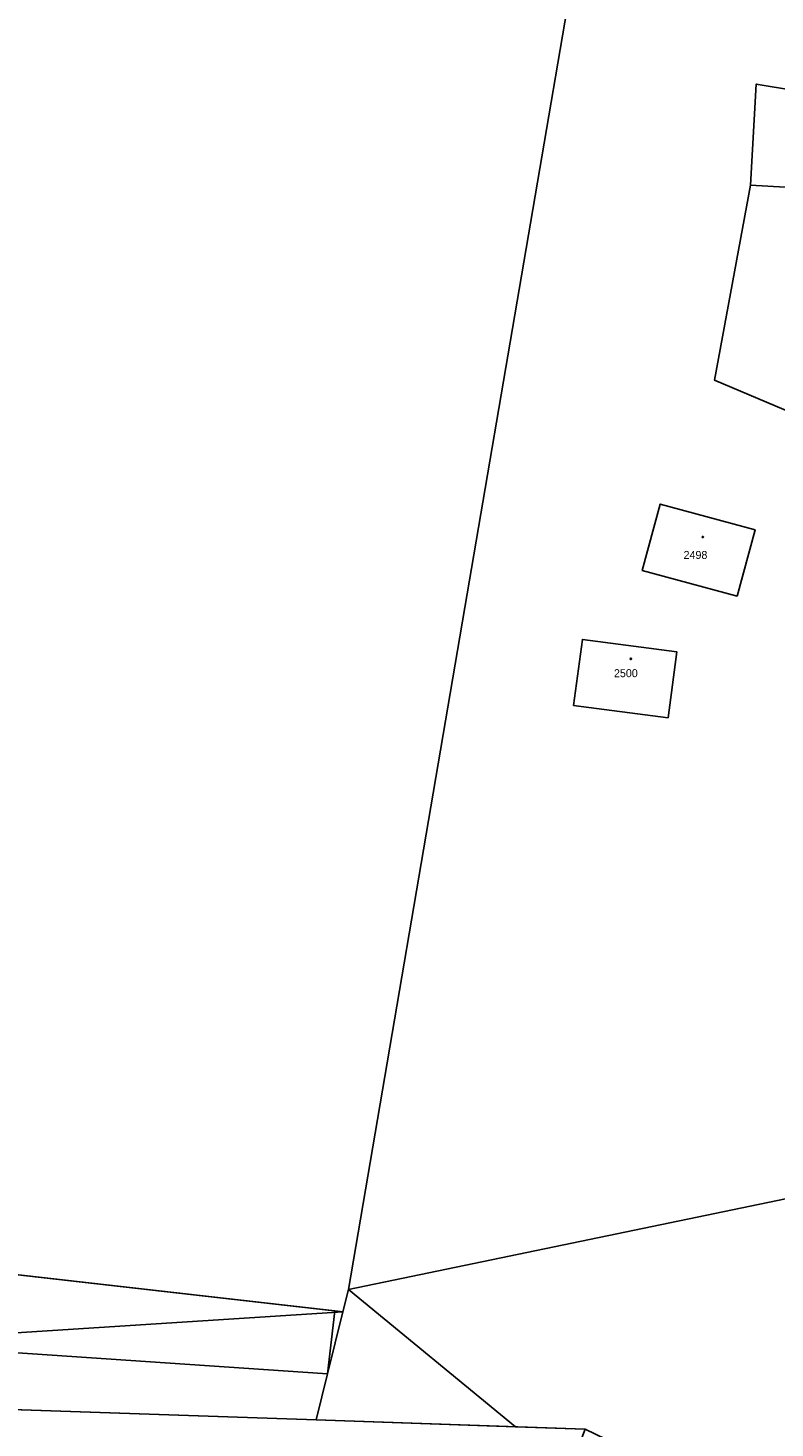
# Model space of a CAD drawing. Extents: x -439750 to -439180, y -1258684 to -1258308.
# Drawn here: x -439415 to -439377.6, y -1258499.7 to -1258429.7 of the extents above; entities that cross this region are included whole.
import ezdxf

# ---------------------------------------------------------------- set-up
doc = ezdxf.new("R2010")
doc.units = 0
doc.layers.add('KATASTER', color=7, linetype='Continuous')
doc.layers.add('UOV', color=7, linetype='Continuous')

# ---------------------------------------------------------------- blocks, each defined once
blk = doc.blocks.new('402')
blk.add_lwpolyline([(0.09, 0.15), (0.18, 0), (0.09, -0.15), (-0.09, -0.15), (-0.18, 0), (-0.09, 0.15), (0.09, 0.15)])

msp = doc.modelspace()

# ---------------------------------------------------------------- linework, layer by layer
at = {"layer": 'KATASTER'}
msp.add_line((-439399.61, -1258493.83), (-439399.97, -1258496.98), dxfattribs=at)
for points in [[(-439342.84, -1258481.76), (-439376.6, -1258488.12), (-439398.93, -1258492.76), (-439393.11, -1258458.67), (-439387.21, -1258424.13), (-439355.89, -1258417.18), (-439355.78, -1258417.92), (-439352.04, -1258443.07), (-439355.61, -1258442.12), (-439357.86, -1258441.52), (-439357.71, -1258440.96), (-439364.32, -1258439.2), (-439364.24, -1258438.91), (-439373.38, -1258436.31), (-439372.9, -1258433.44), (-439378.54, -1258432.5), (-439378.83, -1258437.55), (-439380.62, -1258447.31), (-439375.42, -1258449.5)], [(-439355.61, -1258442.12), (-439356.74, -1258446.39), (-439358.99, -1258445.79), (-439359.74, -1258448.6), (-439376.09, -1258444.64), (-439374.5, -1258437.8), (-439378.83, -1258437.55)], [(-439301.47, -1258497.62), (-439327.16, -1258518.51), (-439334.67, -1258520.03), (-439347.2, -1258516.43), (-439344.2, -1258505.65), (-439348.78, -1258505.65), (-439378.69, -1258503.81), (-439387.09, -1258499.74), (-439400.54, -1258499.28), (-439399.97, -1258496.98), (-439399.2, -1258493.87), (-439398.93, -1258492.76), (-439376.6, -1258488.12), (-439342.84, -1258481.76), (-439340.24, -1258474.48), (-439320.71, -1258462.43), (-439302.65, -1258444.27)], [(-439546.64, -1258459.47), (-439541.07, -1258454.21), (-439536.69, -1258451.87), (-439531.73, -1258450.85), (-439525.5, -1258450.78), (-439520.66, -1258452.66), (-439516.51, -1258455.4), (-439512.86, -1258458.3), (-439509.68, -1258462.08), (-439514.85, -1258480.71), (-439515.19, -1258481.93), (-439503.22, -1258485.2), (-439495.92, -1258486.32), (-439485.72, -1258487.41), (-439470.33, -1258487.62), (-439429.22, -1258494.1), (-439415.96, -1258495.89), (-439399.97, -1258496.98), (-439400.54, -1258499.28), (-439484.47, -1258496.42), (-439507.21, -1258497.49), (-439520.19, -1258486.95), (-439538.17, -1258484.88), (-439548.5, -1258497.7)], [(-439548.5, -1258497.7), (-439538.17, -1258484.88), (-439520.19, -1258486.95), (-439507.21, -1258497.49), (-439484.47, -1258496.42), (-439400.54, -1258499.28), (-439387.09, -1258499.74), (-439411.19, -1258562.66), (-439413.56, -1258566.65), (-439437.77, -1258626.82), (-439438.12, -1258627.38), (-439482.75, -1258611.76), (-439518.67, -1258591.95), (-439550.54, -1258581.84), (-439567.51, -1258574.36), (-439597.45, -1258561.13)]]:
    msp.add_lwpolyline(points, dxfattribs=at)
for points in [[(-439441.83, -1258441.42), (-439442.45, -1258432.5), (-439434.74, -1258431.72), (-439415.05, -1258427.42), (-439387, -1258423.44), (-439387.21, -1258424.13), (-439393.11, -1258458.67), (-439398.93, -1258492.76), (-439399.2, -1258493.87), (-439399.61, -1258493.83), (-439469.01, -1258485.93), (-439465.13, -1258459.21), (-439462.74, -1258442.73), (-439442, -1258444.33)], [(-439349.26, -1258453.19), (-439360.47, -1258451.33), (-439361.08, -1258453.62), (-439375.42, -1258449.5), (-439380.62, -1258447.31), (-439378.83, -1258437.55), (-439378.54, -1258432.5), (-439372.9, -1258433.44), (-439373.38, -1258436.31), (-439364.24, -1258438.91), (-439364.32, -1258439.2), (-439357.71, -1258440.96), (-439357.86, -1258441.52), (-439355.61, -1258442.12), (-439352.04, -1258443.07), (-439351.67, -1258445.55)], [(-439378.6, -1258454.79), (-439379.5, -1258458.1), (-439384.24, -1258456.81), (-439383.34, -1258453.5)], [(-439383.34, -1258453.5), (-439384.24, -1258456.81), (-439379.5, -1258458.1), (-439378.6, -1258454.79)], [(-439382.51, -1258460.89), (-439382.95, -1258464.18), (-439387.67, -1258463.56), (-439387.23, -1258460.26)], [(-439382.95, -1258464.18), (-439382.51, -1258460.89), (-439387.23, -1258460.26), (-439387.67, -1258463.56)], [(-439515.19, -1258481.93), (-439514.85, -1258480.71), (-439469.01, -1258485.93), (-439399.61, -1258493.83), (-439399.2, -1258493.87), (-439399.97, -1258496.98), (-439415.96, -1258495.89), (-439429.22, -1258494.1), (-439470.33, -1258487.62), (-439485.72, -1258487.41), (-439495.92, -1258486.32), (-439503.22, -1258485.2)]]:
    msp.add_lwpolyline(points, close=True, dxfattribs=at)
at = {"layer": 'UOV'}
msp.add_lwpolyline([(-439301.47, -1258497.62), (-439327.16, -1258518.51), (-439334.67, -1258520.03), (-439347.2, -1258516.43), (-439344.2, -1258505.65), (-439348.78, -1258505.65), (-439370.33, -1258504.32), (-439377.96, -1258500.33), (-439383.83, -1258501.32), (-439387.09, -1258499.74), (-439390.58, -1258499.62), (-439398.93, -1258492.76), (-439376.6, -1258488.12), (-439354.47, -1258484.21), (-439339.52, -1258485.43), (-439340.24, -1258474.48), (-439341.1, -1258471.01), (-439320.71, -1258462.43), (-439304.86, -1258436.82)], dxfattribs=at)
for points in [[(-439484.47, -1258496.42), (-439507.21, -1258497.49), (-439513.68, -1258492.23), (-439512.62, -1258492.23), (-439510.04, -1258487.61), (-439512.85, -1258480.94), (-439399.2, -1258493.87), (-439444.59, -1258496.79), (-439457.07, -1258497.35)], [(-439398.93, -1258492.76), (-439390.58, -1258499.62), (-439400.54, -1258499.28), (-439457.07, -1258497.35), (-439444.59, -1258496.79), (-439399.2, -1258493.87)]]:
    msp.add_lwpolyline(points, close=True, dxfattribs=at)

# ---------------------------------------------------------------- block references
at = {"layer": 'KATASTER', "xscale": 0.2, "yscale": 0.20000000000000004}
for p in [(-439381.21, -1258455.14), (-439384.81, -1258461.23)]:
    msp.add_blockref('402', p, dxfattribs=at)

# ---------------------------------------------------------------- texts
at = {"layer": 'KATASTER'}
for s, p in [('2498', (-439382.172, -1258456.24)), ('2500', (-439385.652, -1258462.15))]:
    msp.add_text(s, height=0.4, dxfattribs=at).set_placement(p)

doc.saveas('drawing.dxf')
